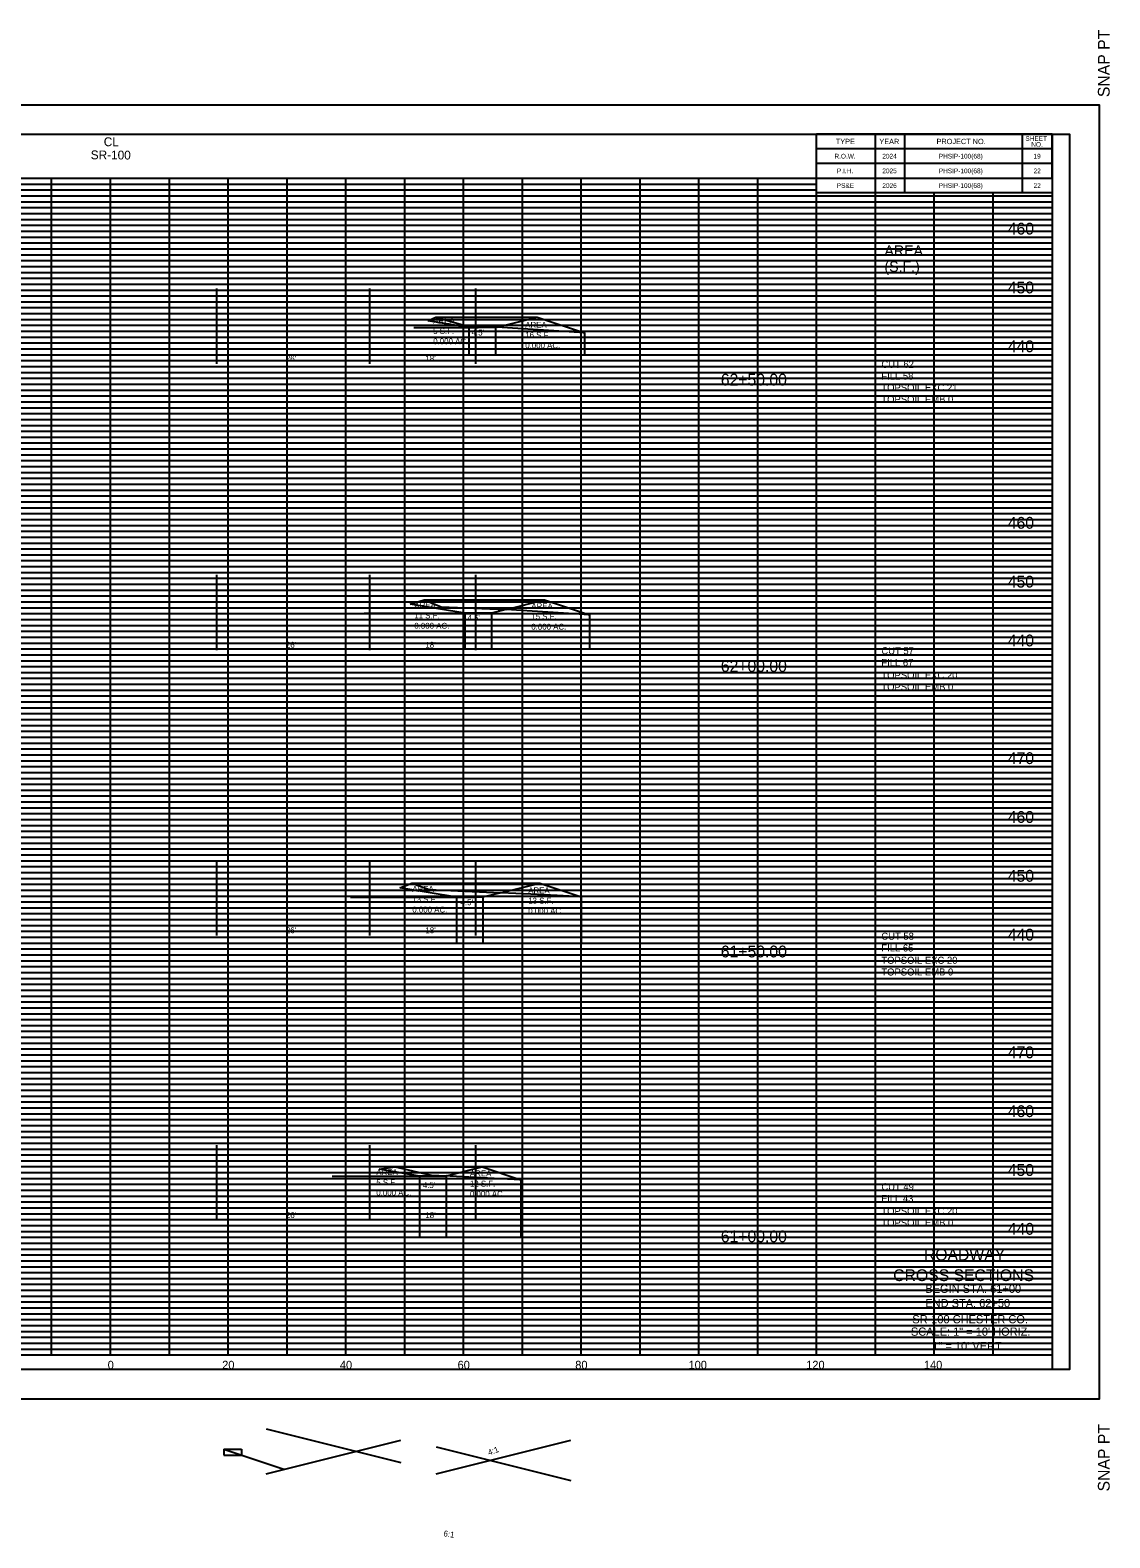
# Model space of a CAD drawing. Extents: x 37 to 1710, y 707 to 2305.
# Drawn here: x 1146.3 to 1329.8, y 1508.9 to 1765.2 of the extents above; entities that cross this region are included whole.
import ezdxf

# ---------------------------------------------------------------- set-up
doc = ezdxf.new("R2010")
doc.units = 0
for name, color, linetype in [('DESIGN - DRAINAGE - Special Ditch Width Text', 7, 'Continuous'), ('DESIGN - SCRATCH - User 1', 7, 'Continuous'), ('DESIGN - SCRATCH - User 2', 7, 'Continuous'), ('DESIGN - SCRATCH - User 3', 7, 'Continuous'), ('DESIGN - SHEET - Corner Text', 7, 'Continuous'), ('DESIGN - SHEET - Light Grid', 7, 'Continuous'), ('DESIGN - SHEET - Linework', 7, 'Continuous'), ('DESIGN - SHEET - Plot Shape', 7, 'Continuous'), ('DESIGN - TYPICAL - Text', 7, 'Continuous')]:
    doc.layers.add(name, color=color, linetype=linetype)

msp = doc.modelspace()

# ---------------------------------------------------------------- linework, layer by layer
at = {"layer": 'DESIGN - SCRATCH - User 1'}
for p, q in [((1285, 1743.75), (1285, 1743.75)), ((1292.5, 1743.75), (1292.5, 1743.75)), ((1305, 1743.75), (1305, 1743.75)), ((1317.5, 1743.75), (1317.5, 1743.75)), ((1285, 1741.25), (1285, 1741.25)), ((1292.5, 1741.25), (1292.5, 1741.25)), ((1305, 1741.25), (1305, 1741.25)), ((1317.5, 1741.25), (1317.5, 1741.25)), ((1186.44, 1527.43), (1209.33, 1521.71)), ((1186.44, 1519.78), (1209.33, 1525.51)), ((1215.33, 1519.78), (1238.21, 1525.51)), ((1215.33, 1524.36), (1238.21, 1518.64))]:
    msp.add_line(p, q, dxfattribs=at)
at = {"layer": 'DESIGN - SCRATCH - User 2'}
for p, q in [((1178, 1721.27), (1178, 1708.46)), ((1204, 1721.27), (1204, 1708.46)), ((1222, 1721.27), (1222, 1708.46)), ((1211.53, 1714.62), (1222.49, 1714.62)), ((1215.26, 1716.41), (1232.53, 1716.41)), ((1220.9, 1714.62), (1220.9, 1710)), ((1225.4, 1714.62), (1225.4, 1710)), ((1240.55, 1713.73), (1240.55, 1710)), ((1178, 1672.59), (1178, 1659.78)), ((1204, 1672.59), (1204, 1659.78)), ((1222, 1672.59), (1222, 1659.78)), ((1213.28, 1668.32), (1233.76, 1668.32)), ((1203.08, 1666.06), (1221.33, 1666.06)), ((1220.22, 1666.06), (1220.22, 1660)), ((1224.72, 1666.06), (1224.72, 1660)), ((1241.41, 1665.77), (1241.41, 1660)), ((1178, 1624.07), (1178, 1611.27)), ((1204, 1624.07), (1204, 1611.27)), ((1222, 1624.07), (1222, 1611.27)), ((1211.23, 1620.19), (1232.94, 1620.19)), ((1200.79, 1617.78), (1221.94, 1617.78)), ((1218.8, 1617.78), (1218.8, 1610)), ((1223.3, 1617.78), (1223.3, 1610)), ((1240, 1617.84), (1240, 1610)), ((1178, 1575.65), (1178, 1562.85)), ((1204, 1575.65), (1204, 1562.85)), ((1222, 1575.65), (1222, 1562.85)), ((1208.36, 1571.95), (1223.18, 1571.95)), ((1197.65, 1570.41), (1217.02, 1570.41)), ((1212.52, 1570.41), (1212.52, 1560)), ((1217.02, 1570.41), (1217.02, 1560)), ((1229.74, 1569.76), (1229.74, 1560)), ((1179.27, 1523.99), (1182.27, 1523.99)), ((1179.27, 1523.99), (1179.27, 1522.99)), ((1179.27, 1523.99), (1189.43, 1520.6)), ((1179.27, 1522.99), (1182.27, 1522.99)), ((1182.27, 1523.99), (1182.27, 1522.99))]:
    msp.add_line(p, q, dxfattribs=at)
at = {"layer": 'DESIGN - SCRATCH - User 3'}
for points in [[(1213.91, 1715.79), (1215.26, 1716.41), (1219.88, 1715.07), (1221.03, 1715.01), (1225.72, 1714.7), (1225.4, 1714.62), (1220.9, 1714.62)], [(1225.72, 1714.7), (1232.53, 1716.41), (1240.55, 1713.73)], [(1210.91, 1667.61), (1213.28, 1668.32), (1216.18, 1667.15), (1227.24, 1666.69), (1224.72, 1666.06), (1220.22, 1666.06)], [(1227.24, 1666.69), (1233.76, 1668.32), (1241.41, 1665.77)], [(1209.18, 1619.38), (1211.23, 1620.19), (1214.13, 1619.11), (1226.35, 1618.54), (1223.3, 1617.78), (1218.8, 1617.78)], [(1226.35, 1618.54), (1232.94, 1620.19), (1240, 1617.84), (1235.93, 1618.09), (1231.43, 1618.3)], [(1205.64, 1571.55), (1208.36, 1571.95), (1214.5, 1570.57), (1217.09, 1570.43), (1217.01, 1570.41), (1212.52, 1570.41)], [(1217.09, 1570.43), (1223.18, 1571.95), (1229.74, 1569.76), (1224.08, 1570.03), (1217.75, 1570.39)]]:
    msp.add_lwpolyline(points, close=True, dxfattribs=at)
at = {"layer": 'DESIGN - SHEET - Light Grid'}
for p, q in [((1000, 1739), (1280, 1739)), ((1000, 1738), (1280, 1738)), ((1000, 1737), (1320, 1737)), ((1000, 1736), (1320, 1736)), ((1000, 1735), (1320, 1735)), ((1000, 1734), (1320, 1734)), ((1000, 1733), (1320, 1733)), ((1000, 1732), (1320, 1732)), ((1000, 1731), (1320, 1731)), ((1000, 1729), (1320, 1729)), ((1000, 1728), (1320, 1728)), ((1000, 1727), (1320, 1727)), ((1000, 1726), (1320, 1726)), ((1000, 1725), (1320, 1725)), ((1000, 1724), (1320, 1724)), ((1000, 1723), (1320, 1723)), ((1000, 1722), (1320, 1722)), ((1000, 1721), (1320, 1721)), ((1000, 1719), (1320, 1719)), ((1000, 1718), (1320, 1718)), ((1000, 1717), (1320, 1717)), ((1000, 1716), (1320, 1716)), ((1000, 1715), (1320, 1715)), ((1000, 1714), (1320, 1714)), ((1000, 1713), (1320, 1713)), ((1000, 1712), (1320, 1712)), ((1000, 1711), (1320, 1711)), ((1000, 1709), (1320, 1709)), ((1000, 1708), (1320, 1708)), ((1000, 1707), (1320, 1707)), ((1000, 1706), (1320, 1706)), ((1000, 1705), (1320, 1705)), ((1000, 1704), (1320, 1704)), ((1000, 1703), (1320, 1703)), ((1000, 1702), (1320, 1702)), ((1000, 1701), (1320, 1701)), ((1000, 1699), (1320, 1699)), ((1000, 1698), (1320, 1698)), ((1000, 1697), (1320, 1697)), ((1000, 1696), (1320, 1696)), ((1000, 1695), (1320, 1695)), ((1000, 1694), (1320, 1694)), ((1000, 1693), (1320, 1693)), ((1000, 1692), (1320, 1692)), ((1000, 1691), (1320, 1691)), ((1000, 1689), (1320, 1689)), ((1000, 1688), (1320, 1688)), ((1000, 1687), (1320, 1687)), ((1000, 1686), (1320, 1686)), ((1000, 1685), (1320, 1685)), ((1000, 1684), (1320, 1684)), ((1000, 1683), (1320, 1683)), ((1000, 1682), (1320, 1682)), ((1000, 1681), (1320, 1681)), ((1000, 1679), (1320, 1679)), ((1000, 1678), (1320, 1678)), ((1000, 1677), (1320, 1677)), ((1000, 1676), (1320, 1676)), ((1000, 1675), (1320, 1675)), ((1000, 1674), (1320, 1674)), ((1000, 1673), (1320, 1673)), ((1000, 1672), (1320, 1672)), ((1000, 1671), (1320, 1671)), ((1000, 1669), (1320, 1669)), ((1000, 1668), (1320, 1668)), ((1000, 1667), (1320, 1667)), ((1000, 1666), (1320, 1666)), ((1000, 1665), (1320, 1665)), ((1000, 1664), (1320, 1664)), ((1000, 1663), (1320, 1663)), ((1000, 1662), (1320, 1662)), ((1000, 1661), (1320, 1661)), ((1000, 1659), (1320, 1659)), ((1000, 1658), (1320, 1658)), ((1000, 1657), (1320, 1657)), ((1000, 1656), (1320, 1656)), ((1000, 1655), (1320, 1655)), ((1000, 1654), (1320, 1654)), ((1000, 1653), (1320, 1653)), ((1000, 1652), (1320, 1652)), ((1000, 1651), (1320, 1651)), ((1000, 1649), (1320, 1649)), ((1000, 1648), (1320, 1648)), ((1000, 1647), (1320, 1647)), ((1000, 1646), (1320, 1646)), ((1000, 1645), (1320, 1645)), ((1000, 1644), (1320, 1644)), ((1000, 1643), (1320, 1643)), ((1000, 1642), (1320, 1642)), ((1000, 1641), (1320, 1641)), ((1000, 1639), (1320, 1639)), ((1000, 1638), (1320, 1638)), ((1000, 1637), (1320, 1637)), ((1000, 1636), (1320, 1636)), ((1000, 1635), (1320, 1635)), ((1000, 1634), (1320, 1634)), ((1000, 1633), (1320, 1633)), ((1000, 1632), (1320, 1632)), ((1000, 1631), (1320, 1631)), ((1000, 1629), (1320, 1629)), ((1000, 1628), (1320, 1628)), ((1000, 1627), (1320, 1627)), ((1000, 1626), (1320, 1626)), ((1000, 1625), (1320, 1625)), ((1000, 1624), (1320, 1624)), ((1000, 1623), (1320, 1623)), ((1000, 1622), (1320, 1622)), ((1000, 1621), (1320, 1621)), ((1000, 1619), (1320, 1619)), ((1000, 1618), (1320, 1618)), ((1000, 1617), (1320, 1617)), ((1000, 1616), (1320, 1616)), ((1000, 1615), (1320, 1615)), ((1000, 1614), (1320, 1614)), ((1000, 1613), (1320, 1613)), ((1000, 1612), (1320, 1612)), ((1000, 1611), (1320, 1611)), ((1000, 1609), (1320, 1609)), ((1000, 1608), (1320, 1608)), ((1000, 1607), (1320, 1607)), ((1000, 1606), (1320, 1606)), ((1000, 1605), (1320, 1605)), ((1000, 1604), (1320, 1604)), ((1000, 1603), (1320, 1603)), ((1000, 1602), (1320, 1602)), ((1000, 1601), (1320, 1601)), ((1000, 1599), (1320, 1599)), ((1000, 1598), (1320, 1598)), ((1000, 1597), (1320, 1597)), ((1000, 1596), (1320, 1596)), ((1000, 1595), (1320, 1595)), ((1000, 1594), (1320, 1594)), ((1000, 1593), (1320, 1593)), ((1000, 1592), (1320, 1592)), ((1000, 1591), (1320, 1591)), ((1000, 1589), (1320, 1589)), ((1000, 1588), (1320, 1588)), ((1000, 1587), (1320, 1587)), ((1000, 1586), (1320, 1586)), ((1000, 1585), (1320, 1585)), ((1000, 1584), (1320, 1584)), ((1000, 1583), (1320, 1583)), ((1000, 1582), (1320, 1582)), ((1000, 1581), (1320, 1581)), ((1000, 1579), (1320, 1579)), ((1000, 1578), (1320, 1578)), ((1000, 1577), (1320, 1577)), ((1000, 1576), (1320, 1576)), ((1000, 1575), (1320, 1575)), ((1000, 1574), (1320, 1574)), ((1000, 1573), (1320, 1573)), ((1000, 1572), (1320, 1572)), ((1000, 1571), (1320, 1571)), ((1000, 1569), (1320, 1569)), ((1000, 1568), (1320, 1568)), ((1000, 1567), (1320, 1567)), ((1000, 1566), (1320, 1566)), ((1000, 1565), (1320, 1565)), ((1000, 1564), (1320, 1564)), ((1000, 1563), (1320, 1563)), ((1000, 1562), (1320, 1562)), ((1000, 1561), (1320, 1561)), ((1000, 1559), (1320, 1559)), ((1000, 1558), (1320, 1558)), ((1000, 1557), (1320, 1557)), ((1000, 1556), (1320, 1556)), ((1000, 1555), (1320, 1555)), ((1000, 1554), (1320, 1554)), ((1000, 1553), (1320, 1553)), ((1000, 1552), (1320, 1552)), ((1000, 1551), (1320, 1551)), ((1000, 1549), (1320, 1549)), ((1000, 1548), (1320, 1548)), ((1000, 1547), (1320, 1547)), ((1000, 1546), (1320, 1546)), ((1000, 1545), (1320, 1545)), ((1000, 1544), (1320, 1544)), ((1000, 1543), (1320, 1543)), ((1000, 1542), (1320, 1542)), ((1000, 1541), (1320, 1541))]:
    msp.add_line(p, q, dxfattribs=at)
at = {"layer": 'DESIGN - SHEET - Linework'}
for p, q in [((1320, 1747.5), (1280, 1747.5)), ((1280, 1740), (1280, 1747.5)), ((1290, 1740), (1290, 1747.5)), ((1295, 1737.5), (1295, 1747.5)), ((1315, 1737.5), (1315, 1747.5)), ((1320, 1740), (1320, 1747.5)), ((1320, 1745), (1280, 1745)), ((1000, 1740), (1320, 1740)), ((1150, 1540), (1150, 1740)), ((1160, 1540), (1160, 1740)), ((1170, 1540), (1170, 1740)), ((1180, 1540), (1180, 1740)), ((1190, 1540), (1190, 1740)), ((1200, 1540), (1200, 1740)), ((1210, 1540), (1210, 1740)), ((1220, 1540), (1220, 1740)), ((1230, 1540), (1230, 1740)), ((1240, 1540), (1240, 1740)), ((1250, 1540), (1250, 1740)), ((1260, 1540), (1260, 1740)), ((1270, 1540), (1270, 1740)), ((1320, 1742.5), (1280, 1742.5)), ((1280, 1540), (1280, 1740)), ((1290, 1540), (1290, 1740)), ((1320, 1737.5), (1280, 1737.5)), ((1300, 1540), (1300, 1737.5)), ((1310, 1540), (1310, 1737.5)), ((1000, 1730), (1320, 1730)), ((1000, 1720), (1320, 1720)), ((1000, 1710), (1320, 1710)), ((1000, 1700), (1320, 1700)), ((1000, 1690), (1320, 1690)), ((1000, 1680), (1320, 1680)), ((1000, 1670), (1320, 1670)), ((1000, 1660), (1320, 1660)), ((1000, 1650), (1320, 1650)), ((1000, 1640), (1320, 1640)), ((1000, 1630), (1320, 1630)), ((1000, 1620), (1320, 1620)), ((1000, 1610), (1320, 1610)), ((1000, 1600), (1320, 1600)), ((1000, 1590), (1320, 1590)), ((1000, 1580), (1320, 1580)), ((1000, 1570), (1320, 1570)), ((1000, 1560), (1320, 1560)), ((1000, 1550), (1320, 1550)), ((1000, 1540), (1320, 1540))]:
    msp.add_line(p, q, dxfattribs=at)
for points in [[(988, 1752.5), (1328, 1752.5), (1328, 1532.5), (988, 1532.5)], [(1000, 1747.5), (1320, 1747.5), (1320, 1537.5), (1000, 1537.5)]]:
    msp.add_lwpolyline(points, close=True, dxfattribs=at)
at = {"layer": 'DESIGN - SHEET - Plot Shape'}
msp.add_lwpolyline([(993, 1747.5), (1323, 1747.5), (1323, 1537.5), (993, 1537.5)], close=True, dxfattribs=at)

# ---------------------------------------------------------------- texts
at = {"layer": 'DESIGN - DRAINAGE - Special Ditch Width Text'}
for s, p in [('CL', (1158.85, 1745.45)), ('SR-100', (1156.64, 1743.22))]:
    msp.add_text(s, height=1.5, rotation=359.6675, dxfattribs=at).set_placement(p)
at = {"layer": 'DESIGN - SCRATCH - User 1'}
for s, rotation, p in [('4:1', 20.3595, (1224.34, 1522.9)), ('6:1', 350.5377, (1216.53, 1509.2))]:
    msp.add_text(s, height=1, rotation=rotation, dxfattribs=at).set_placement(p)
at = {"layer": 'DESIGN - SCRATCH - User 2'}
for s, p in [("4.5'", (1221.37, 1713.27)), ("26'", (1189.81, 1708.87)), ("18'", (1213.51, 1708.87)), ("4.5'", (1220.66, 1664.78)), ("26'", (1189.81, 1660.2)), ("18'", (1213.51, 1660.2)), ("4.5'", (1219.49, 1616.44)), ("26'", (1189.81, 1611.68)), ("18'", (1213.51, 1611.68)), ("4.5'", (1213.07, 1568.36)), ("26'", (1189.81, 1563.26)), ("18'", (1213.51, 1563.26))]:
    msp.add_text(s, height=1, dxfattribs=at).set_placement(p)
at = {"layer": 'DESIGN - SCRATCH - User 3'}
for s, p in [('AREA', (1214.84, 1715.28)), ('5 S.F.', (1214.84, 1713.53)), ('AREA', (1230.48, 1714.59)), ('0.000 AC.', (1214.84, 1711.78)), ('0.000 AC.', (1230.48, 1711.09)), ('16 S.F.', (1230.48, 1712.84)), ('AREA', (1211.63, 1666.93)), ('11 S.F.', (1211.63, 1665.18)), ('AREA', (1231.51, 1666.77)), ('15 S.F.', (1231.51, 1665.02)), ('0.000 AC.', (1211.63, 1663.43)), ('0.000 AC.', (1231.51, 1663.27)), ('AREA', (1211.29, 1618.7)), ('13 S.F.', (1211.29, 1616.95)), ('AREA', (1230.99, 1618.46)), ('13 S.F.', (1230.99, 1616.71)), ('0.000 AC.', (1211.29, 1615.2)), ('0.000 AC.', (1230.99, 1614.96)), ('AREA', (1205.17, 1570.57)), ('AREA', (1221.08, 1570.36)), ('5 S.F.', (1205.17, 1568.82)), ('12 S.F.', (1221.08, 1568.61)), ('0.000 AC.', (1205.17, 1567.07)), ('0.000 AC.', (1221.08, 1566.86))]:
    msp.add_text(s, height=1, dxfattribs=at).set_placement(p)
at = {"layer": 'DESIGN - SHEET - Corner Text'}
for s, p in [('  SNAP PT', (1329.8, 1752.3)), ('SNAP PT  ', (1329.8, 1516.8))]:
    msp.add_text(s, height=2, rotation=90, dxfattribs=at).set_placement(p)
for s, height, p in [('R.O.W.', 0.8, (1283.02, 1743.35)), ('2024', 0.8, (1291.16, 1743.35)), ('PHSIP-100(68)', 0.8, (1300.75, 1743.35)), ('19', 0.8, (1316.86, 1743.35)), ('P.I.H.', 0.8, (1283.45, 1740.85)), ('2025', 0.8, (1291.16, 1740.85)), ('PHSIP-100(68)', 0.8, (1300.75, 1740.85)), ('22', 0.8, (1316.87, 1740.85)), ('PS&E', 0.8, (1283.42, 1738.35)), ('2026', 0.8, (1291.16, 1738.35)), ('PHSIP-100(68)', 0.8, (1300.75, 1738.35)), ('22', 0.8, (1316.87, 1738.35)), ('ROADWAY ', 2, (1298.23, 1556.05)), ('CROSS SECTIONS', 2, (1293.01, 1552.55)), ('BEGIN STA. 61+00', 1.4, (1298.47, 1550.55)), ('END STA. 62+50', 1.4, (1298.47, 1548.1)), ('SR-100 CHESTER CO.', 1.4, (1296.25, 1545.37)), ('SCALE: 1" = 10\' HORIZ.', 1.4, (1296.02, 1543.26)), ('       1" = 10\' VERT.   ', 1.4, (1296.02, 1540.81))]:
    msp.add_text(s, height=height, dxfattribs=at).set_placement(p)
at = {"layer": 'DESIGN - SHEET - Light Grid'}
for s, height, p in [('TYPE', 0.9, (1283.26, 1745.8)), ('YEAR', 0.9, (1290.66, 1745.8)), ('PROJECT NO.', 0.9, (1300.38, 1745.8)), ('SHEET', 0.8, (1315.47, 1746.35)), ('NO.', 0.8, (1316.47, 1745.35))]:
    msp.add_text(s, height=height, dxfattribs=at).set_placement(p)
at = {"layer": 'DESIGN - TYPICAL - Text'}
for s, height, p in [('     460     ', 2, (1308.77, 1730.43)), ('AREA ', 1.8, (1291.52, 1726.79)), ('(S.F.)', 1.8, (1291.52, 1724.09)), ('     450     ', 2, (1308.77, 1720.43)), ('     440     ', 2, (1308.77, 1710.43)), ('     62+50.00     ', 2, (1260, 1704.77)), ('CUT 62', 1.2, (1291, 1707.77)), ('FILL 58', 1.2, (1291, 1705.77)), ('TOPSOIL EXC 21', 1.2, (1291, 1703.81)), ('TOPSOIL EMB 0', 1.2, (1291, 1701.82)), ('     460     ', 2, (1308.77, 1680.43)), ('     450     ', 2, (1308.77, 1670.43)), ('     440     ', 2, (1308.77, 1660.43)), ('     62+00.00     ', 2, (1260, 1656.09)), ('CUT 57', 1.2, (1291, 1659.09)), ('FILL 67', 1.2, (1291, 1657.09)), ('TOPSOIL EXC 20', 1.2, (1291, 1654.94)), ('TOPSOIL EMB 0', 1.2, (1291, 1652.95)), ('     470     ', 2, (1308.77, 1640.43)), ('     460     ', 2, (1308.77, 1630.43)), ('     450     ', 2, (1308.77, 1620.43)), ('     440     ', 2, (1308.77, 1610.43)), ('     61+50.00     ', 2, (1260, 1607.57)), ('CUT 58', 1.2, (1291, 1610.57)), ('FILL 65', 1.2, (1291, 1608.57)), ('TOPSOIL EXC 20', 1.2, (1291, 1606.48)), ('TOPSOIL EMB 0', 1.2, (1291, 1604.49)), ('     470     ', 2, (1308.77, 1590.43)), ('     460     ', 2, (1308.77, 1580.43)), ('     450     ', 2, (1308.77, 1570.43)), ('CUT 49', 1.2, (1291, 1567.99)), ('FILL 43', 1.2, (1291, 1565.99)), ('TOPSOIL EXC 20', 1.2, (1291, 1563.85)), ('     61+00.00     ', 2, (1260, 1559.15)), ('TOPSOIL EMB 0', 1.2, (1291, 1561.86)), ('     440     ', 2, (1308.77, 1560.43)), ('     0     ', 1.4, (1156.92, 1537.6)), ('     0     ', 1.4, (1156.92, 1537.6)), ('     20     ', 1.4, (1176.38, 1537.6)), ('     40     ', 1.4, (1196.38, 1537.6)), ('     60     ', 1.4, (1216.38, 1537.6)), ('     80     ', 1.4, (1236.38, 1537.6)), ('     100     ', 1.4, (1255.63, 1537.6)), ('     120     ', 1.4, (1275.63, 1537.6)), ('     140     ', 1.4, (1295.63, 1537.6))]:
    msp.add_text(s, height=height, dxfattribs=at).set_placement(p)

doc.saveas('drawing.dxf')
